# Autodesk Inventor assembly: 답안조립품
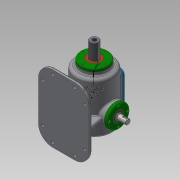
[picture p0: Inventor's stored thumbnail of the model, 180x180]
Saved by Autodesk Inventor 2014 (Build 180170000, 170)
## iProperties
Created: 2019-10
Part Number: 답안조립품
Document SubType Name: Assembly
Designer: NET
Author: NET
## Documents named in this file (17)
- C:\Users\net\Desktop\391004V1043!\답안조립품.iam
- C:\Users\net\Desktop\391004V1043\본체.ipt
- C:\Users\net\Desktop\391004V1043\가변스프링.ipt
- C:\Users\net\Desktop\391004V1043\개스킷 A.ipt
- C:\Users\net\Desktop\391004V1043\개스킷 B.ipt
- C:\Users\net\Desktop\391004V1043\고정플레이트.ipt
- C:\Users\net\Desktop\391004V1043\베어링 6205.ipt
- 베어링 6205.ipt
- C:\Users\net\Desktop\391004V1043\볼트 M4x0.7.ipt
- C:\Users\net\Desktop\391004V1043\부시.ipt
- C:\Users\net\Desktop\391004V1043\상부커버.ipt
- C:\Users\net\Desktop\391004V1043\슬라이드 커버.ipt
- C:\Users\net\Desktop\391004V1043\슬라이드.ipt
- C:\Users\net\Desktop\391004V1043\오일 실 25 38 8.ipt
- C:\Users\net\Desktop\391004V1043\육각머리볼트 M4.ipt
- C:\Users\net\Desktop\391004V1043\축 커버.ipt
- C:\Users\net\Desktop\391004V1043\편심축.ipt
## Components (17 placed, 5 different names)
1. 가변스프링:1
2. 개스킷 A:1
3. 개스킷 B:1
4. 고정플레이트:1
5. 개스킷 B:2
6. M4x0.7:1
7. M4x0.7:4
8. M4x0.7:5
9. M4x0.7:6
10. M4x0.7:3
11. M4x0.7:7
12. M4x0.7:8
13. M4x0.7:9
14. M4x0.7:2
15. M4x0.7:10
16. M4x0.7:11
17. M4x0.7:12
